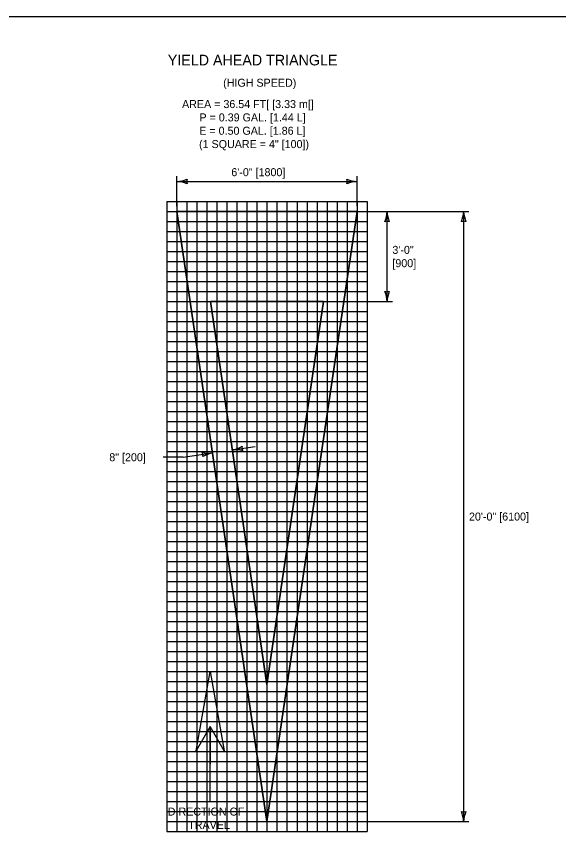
# Model space of a CAD drawing. Extents: x 49948.7 to 50021, y 49977 to 50017.6.
# Drawn here: x 50003.75 to 50007.81, y 49992.83 to 49999 of the extents above; entities that cross this region are included whole.
import ezdxf

# ---------------------------------------------------------------- set-up
doc = ezdxf.new("R2010")
doc.units = 0
for name, color, linetype in [('Level 1', 7, 'Continuous'), ('Level 2', 7, 'Continuous'), ('Level 3', 7, 'Continuous'), ('Level 9', 7, 'Continuous')]:
    doc.layers.add(name, color=color, linetype=linetype)

msp = doc.modelspace()

# ---------------------------------------------------------------- linework, layer by layer
at = {"layer": 'Level 1'}
for p, q in [((50005.6272, 49992.9614), (50004.9522, 49997.5364)), ((50004.9522, 49997.5364), (50006.3022, 49997.5364)), ((50005.6272, 49992.9614), (50004.9522, 49997.5364)), ((50004.9522, 49997.5364), (50006.3022, 49997.5364)), ((50006.3022, 49997.5364), (50004.9522, 49997.5364)), ((50004.9522, 49997.5364), (50005.6272, 49992.9614)), ((50006.3022, 49997.5364), (50005.6272, 49992.9614)), ((50006.3022, 49997.5364), (50005.6272, 49992.9614)), ((50005.6272, 49992.9614), (50006.3022, 49997.5364)), ((50006.051, 49996.8614), (50005.2035, 49996.8614)), ((50005.2035, 49996.8614), (50005.6272, 49993.989)), ((50006.051, 49996.8614), (50005.2035, 49996.8614)), ((50005.2035, 49996.8614), (50005.6272, 49993.989)), ((50005.6272, 49993.989), (50005.2035, 49996.8614)), ((50005.2035, 49996.8614), (50006.051, 49996.8614)), ((50005.6272, 49993.989), (50006.051, 49996.8614)), ((50005.6272, 49993.989), (50006.051, 49996.8614)), ((50006.051, 49996.8614), (50005.6272, 49993.989)), ((50005.2017, 49993.1066), (50005.2021, 49993.6741)), ((50005.2022, 49993.1065), (50005.2025, 49993.6742))]:
    msp.add_line(p, q, dxfattribs=at)
for points in [[(49999.3835, 49998.9992), (50016.7501, 49998.9992), (50016.7501, 49987.7988), (49999.3835, 49987.7988)], [(50005.0973, 49993.4927), (50005.2023, 49994.0865), (50005.3073, 49993.4926), (50005.2019, 49993.6738)]]:
    msp.add_lwpolyline(points, close=True, dxfattribs=at)
at = {"layer": 'Level 2'}
msp.add_line((50006.1537, 49996.8614), (50006.1539, 49996.8614), dxfattribs=at)
at = {"layer": 'Level 3'}
for p, q in [((50004.9522, 49997.5764), (50004.9522, 49997.8014)), ((50004.9522, 49997.7614), (50006.3022, 49997.7614)), ((50006.3022, 49997.5764), (50006.3022, 49997.8014)), ((50006.3422, 49997.5364), (50007.1415, 49997.5364)), ((50006.5272, 49996.8614), (50006.5272, 49997.5364)), ((50007.1015, 49997.5364), (50007.1015, 49992.9614)), ((50006.2427, 49996.8614), (50006.5672, 49996.8614)), ((50005.3677, 49995.7481), (50005.5394, 49995.7734)), ((50004.9995, 49995.6938), (50005.2193, 49995.7262)), ((50004.9995, 49995.6938), (50004.85, 49995.6938)), ((50005.6672, 49992.9614), (50007.1415, 49992.9614))]:
    msp.add_line(p, q, dxfattribs=at)
for centre, radius, start, end in [((50004.9408, 49997.9941), 0.233, 272.82731, 292.07716), ((50004.9431, 49997.5392), 0.2223, 67.45601, 87.63952), ((50005.0805, 49997.7614), 0.0548, 162.13882, 197.86118), ((50006.3114, 49997.9835), 0.2223, 247.45601, 267.63952), ((50006.174, 49997.7614), 0.0548, 342.13882, 17.86118), ((50006.3137, 49997.5287), 0.233, 92.82731, 112.07716), ((50006.3051, 49997.5455), 0.2223, 337.45601, 357.63952), ((50006.76, 49997.5479), 0.233, 182.82731, 202.07716), ((50006.8794, 49997.5455), 0.2223, 337.45601, 357.63952), ((50007.3342, 49997.5479), 0.233, 182.82731, 202.07716), ((50006.5272, 49997.4082), 0.0548, 72.13882, 107.86118), ((50007.1015, 49997.4082), 0.0548, 72.13882, 107.86118), ((50006.5272, 49996.9896), 0.0548, 252.13882, 287.86118), ((50006.2945, 49996.8499), 0.233, 2.82731, 22.07716), ((50006.7494, 49996.8522), 0.2223, 157.45601, 177.63952), ((50005.196, 49995.9473), 0.2223, 255.84894, 276.03244), ((50005.0925, 49995.7075), 0.0548, 350.53174, 26.25411), ((50005.2647, 49995.4977), 0.233, 101.22024, 120.47009), ((50007.1015, 49993.0896), 0.0548, 252.13882, 287.86118), ((50006.8688, 49992.9499), 0.233, 2.82731, 22.07716), ((50007.3237, 49992.9522), 0.2223, 157.45601, 177.63952)]:
    msp.add_arc(centre, radius, start, end, dxfattribs=at)
for centre, major_axis, start_param, end_param in [((50005.3224, 49995.9766), (0.2307, 0.034), 4.761823, 5.097796), ((50005.4946, 49995.7668), (-0.0542, -0.008), 5.971537, 6.59501), ((50005.3911, 49995.527), (0.2201, 0.0325), 1.177418, 1.529686)]:
    msp.add_ellipse(centre, major_axis=major_axis, ratio=0.999336, start_param=start_param, end_param=end_param, dxfattribs=at)
at = {"layer": 'Level 9'}
for p, q in [((50004.8772, 49997.6114), (50004.8772, 49992.8864)), ((50004.8772, 49997.6114), (50006.3772, 49997.6114)), ((50004.9522, 49997.6114), (50004.9522, 49992.8864)), ((50005.0272, 49997.6114), (50005.0272, 49992.8864)), ((50005.1022, 49997.6114), (50005.1022, 49992.8864)), ((50005.1772, 49997.6114), (50005.1772, 49992.8864)), ((50005.2522, 49997.6114), (50005.2522, 49992.8864)), ((50005.3272, 49997.6114), (50005.3272, 49992.8864)), ((50005.4022, 49997.6114), (50005.4022, 49992.8864)), ((50005.4772, 49997.6114), (50005.4772, 49992.8864)), ((50005.5522, 49997.6114), (50005.5522, 49992.8864)), ((50005.6272, 49997.6114), (50005.6272, 49992.8864)), ((50005.7022, 49997.6114), (50005.7022, 49992.8864)), ((50005.7772, 49997.6114), (50005.7772, 49992.8864)), ((50005.8522, 49997.6114), (50005.8522, 49992.8864)), ((50005.9272, 49997.6114), (50005.9272, 49992.8864)), ((50006.0022, 49997.6114), (50006.0022, 49992.8864)), ((50006.0772, 49997.6114), (50006.0772, 49992.8864)), ((50006.1522, 49997.6114), (50006.1522, 49992.8864)), ((50006.2272, 49997.6114), (50006.2272, 49992.8864)), ((50006.3022, 49997.6114), (50006.3022, 49992.8864)), ((50006.3772, 49997.6114), (50006.3772, 49992.8864)), ((50004.8772, 49997.5364), (50006.3772, 49997.5364)), ((50004.8772, 49997.4614), (50006.3772, 49997.4614)), ((50004.8772, 49997.3864), (50006.3772, 49997.3864)), ((50004.8772, 49997.3114), (50006.3772, 49997.3114)), ((50004.8772, 49997.2364), (50006.3772, 49997.2364)), ((50004.8772, 49997.1614), (50006.3772, 49997.1614)), ((50004.8772, 49997.0864), (50006.3772, 49997.0864)), ((50004.8772, 49997.0114), (50006.3772, 49997.0114)), ((50004.8772, 49996.9364), (50006.3772, 49996.9364)), ((50004.8772, 49996.8614), (50006.3772, 49996.8614)), ((50004.8772, 49996.7864), (50006.3772, 49996.7864)), ((50004.8772, 49996.7114), (50006.3772, 49996.7114)), ((50004.8772, 49996.7114), (50006.3772, 49996.7114)), ((50004.8772, 49996.6364), (50006.3772, 49996.6364)), ((50004.8772, 49996.5614), (50006.3772, 49996.5614)), ((50004.8772, 49996.4864), (50006.3772, 49996.4864)), ((50004.8772, 49996.4114), (50006.3772, 49996.4114)), ((50004.8772, 49996.3364), (50006.3772, 49996.3364)), ((50004.8772, 49996.2614), (50006.3772, 49996.2614)), ((50004.8772, 49996.1864), (50006.3772, 49996.1864)), ((50004.8772, 49996.1114), (50006.3772, 49996.1114)), ((50004.8772, 49996.0364), (50006.3772, 49996.0364)), ((50004.8772, 49995.9614), (50006.3772, 49995.9614)), ((50004.8772, 49995.8864), (50006.3772, 49995.8864)), ((50004.8772, 49995.8114), (50006.3772, 49995.8114)), ((50004.8772, 49995.7364), (50006.3772, 49995.7364)), ((50004.8772, 49995.6614), (50006.3772, 49995.6614)), ((50004.8772, 49995.5864), (50006.3772, 49995.5864)), ((50004.8772, 49995.5114), (50006.3772, 49995.5114)), ((50004.8772, 49995.4364), (50006.3772, 49995.4364)), ((50004.8772, 49995.3614), (50006.3772, 49995.3614)), ((50004.8772, 49995.2864), (50006.3772, 49995.2864)), ((50004.8772, 49995.2114), (50006.3772, 49995.2114)), ((50004.8772, 49995.1364), (50006.3772, 49995.1364)), ((50004.8772, 49995.0614), (50006.3772, 49995.0614)), ((50004.8772, 49994.9864), (50006.3772, 49994.9864)), ((50004.8772, 49994.9114), (50006.3772, 49994.9114)), ((50004.8772, 49994.8364), (50006.3772, 49994.8364)), ((50004.8772, 49994.7614), (50006.3772, 49994.7614)), ((50004.8772, 49994.6864), (50006.3772, 49994.6864)), ((50004.8772, 49994.6114), (50006.3772, 49994.6114)), ((50004.8772, 49994.5364), (50006.3772, 49994.5364)), ((50004.8772, 49994.4614), (50006.3772, 49994.4614)), ((50004.8772, 49994.3864), (50006.3772, 49994.3864)), ((50004.8772, 49994.3114), (50006.3772, 49994.3114)), ((50004.8772, 49994.2364), (50006.3772, 49994.2364)), ((50004.8772, 49994.1614), (50006.3772, 49994.1614)), ((50004.8772, 49994.0864), (50006.3772, 49994.0864)), ((50004.8772, 49994.0114), (50006.3772, 49994.0114)), ((50004.8772, 49993.9364), (50006.3772, 49993.9364)), ((50004.8772, 49993.8614), (50006.3772, 49993.8614)), ((50004.8772, 49993.7864), (50006.3772, 49993.7864)), ((50004.8772, 49993.7114), (50006.3772, 49993.7114)), ((50004.8772, 49993.6364), (50006.3772, 49993.6364)), ((50004.8772, 49993.5614), (50006.3772, 49993.5614)), ((50004.8772, 49993.4864), (50006.3772, 49993.4864)), ((50004.8772, 49993.4114), (50006.3772, 49993.4114)), ((50004.8772, 49993.3364), (50006.3772, 49993.3364)), ((50004.8772, 49993.2614), (50006.3772, 49993.2614)), ((50004.8772, 49993.1864), (50006.3772, 49993.1864)), ((50004.8772, 49993.1114), (50006.3772, 49993.1114)), ((50004.8772, 49993.0364), (50006.3772, 49993.0364)), ((50004.8772, 49992.9614), (50006.3772, 49992.9614)), ((50004.8772, 49992.8864), (50006.3772, 49992.8864))]:
    msp.add_line(p, q, dxfattribs=at)

# ---------------------------------------------------------------- texts
at = {"layer": 'Level 2'}
for s, height, p in [('YIELD AHEAD TRIANGLE', 0.08, (50004.8834, 49998.6322)), ('(HIGH SPEED)', 0.06, (50005.2986, 49998.4722)), ('AREA = 36.54 FT[ [3.33 m[]', 0.06, (50004.9905, 49998.3122)), ('P = 0.39 GAL. [1.44 L]', 0.06, (50005.1209, 49998.2122)), ('E = 0.50 GAL. [1.86 L]', 0.06, (50005.1197, 49998.1122)), ('(1 SQUARE = 4" [100])', 0.06, (50005.1181, 49998.0122)), ('6\'-0" [1800]', 0.06, (50005.3597, 49997.8014)), ('3\'-0"', 0.06, (50006.5672, 49997.2189)), ('[900]', 0.06, (50006.5672, 49997.1189)), ('8" [200]', 0.06, (50004.445, 49995.6638)), ('20\'-0" [6100]', 0.06, (50007.1415, 49995.2189)), ('DIRECTION OF', 0.06, (50004.8833, 49993.0065)), ('TRAVEL', 0.06, (50005.0368, 49992.9065))]:
    msp.add_text(s, height=height, dxfattribs=at).set_placement(p)

doc.saveas('drawing.dxf')
